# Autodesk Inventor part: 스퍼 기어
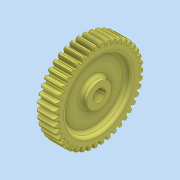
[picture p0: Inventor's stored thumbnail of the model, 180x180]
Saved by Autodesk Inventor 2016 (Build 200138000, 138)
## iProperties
Created: 2024-09
Part Number: 스퍼 기어
Material: 일반
Document SubType Name: Modeling
Designer: pc-7
Density: 1 g/cm^3
Appearance: 기본값
Author: jhkim
Sending System: Autodesk Inventor 2025
Preprocessor: ST-DEVELOPER v20
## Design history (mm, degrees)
node "스퍼 기어1"
node "솔리드2"
node "솔리드1"
